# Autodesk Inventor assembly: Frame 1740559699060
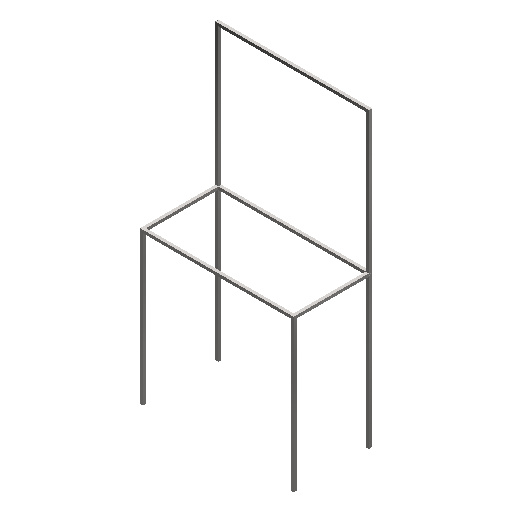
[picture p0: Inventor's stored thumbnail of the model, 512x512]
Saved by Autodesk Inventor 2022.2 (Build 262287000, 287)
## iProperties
_FrameDoc: Frame Assembly
_Version: 25.0.0
Created: 2025-02
Part Number: Frame 1740559699060
Document SubType Name: Assembly
Designer: 18907419
Author: 18907419
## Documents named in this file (13)
- C:\Users\18907419\Desktop\frigo\tavolo\Frame\Frame 1740559699060.iam
- C:\Users\18907419\Desktop\frigo\tavolo\Frame\Skeleton 1740559699061.ipt
- C:\Users\18907419\Desktop\frigo\tavolo\Frame\ISO 1035_2 20x 20 1740559700727.ipt
- C:\Users\18907419\Desktop\frigo\tavolo\Frame\ISO 1035_2 20x 20 1740559700770.ipt
- C:\Users\18907419\Desktop\frigo\tavolo\Frame\ISO 1035_2 20x 20 1740559700812.ipt
- C:\Users\18907419\Desktop\frigo\tavolo\Frame\ISO 1035_2 20x 20 1740559700854.ipt
- C:\Users\18907419\Desktop\frigo\tavolo\Frame\ISO 1035_2 20x 20 1740559750143.ipt
- C:\Users\18907419\Desktop\frigo\tavolo\Frame\ISO 1035_2 20x 20 1740559750187.ipt
- C:\Users\18907419\Desktop\frigo\tavolo\Frame\ISO 1035_2 20x 20 1740559750230.ipt
- C:\Users\18907419\Desktop\frigo\tavolo\Frame\ISO 1035_2 20x 20 1740559750273.ipt
- C:\Users\18907419\Desktop\frigo\tavolo\Frame\ISO 1035_2 20x 20 1740734224184.ipt
- C:\Users\18907419\Desktop\frigo\tavolo\Frame\ISO 1035_2 20x 20 1740734224227.ipt
- C:\Users\18907419\Desktop\frigo\tavolo\Frame\ISO 1035_2 20x 20 1740734224273.ipt
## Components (12 placed, 5 different names)
1. Reference Skeleton
2. ISO 1035/2 20x 20 - 1020:1
3. ISO 1035/2 20x 20 - 520:1
4. ISO 1035/2 20x 20 - 1020:2
5. ISO 1035/2 20x 20 - 520:2
6. ISO 1035/2 20x 20 - 1010:3
7. ISO 1035/2 20x 20 - 1010:4
8. ISO 1035/2 20x 20 - 1010:5
9. ISO 1035/2 20x 20 - 1010:6
10. ISO 1035/2 20x 20 - 1020:7
11. ISO 1035/2 20x 20 - 939,69:1
12. ISO 1035/2 20x 20 - 939,69:2
